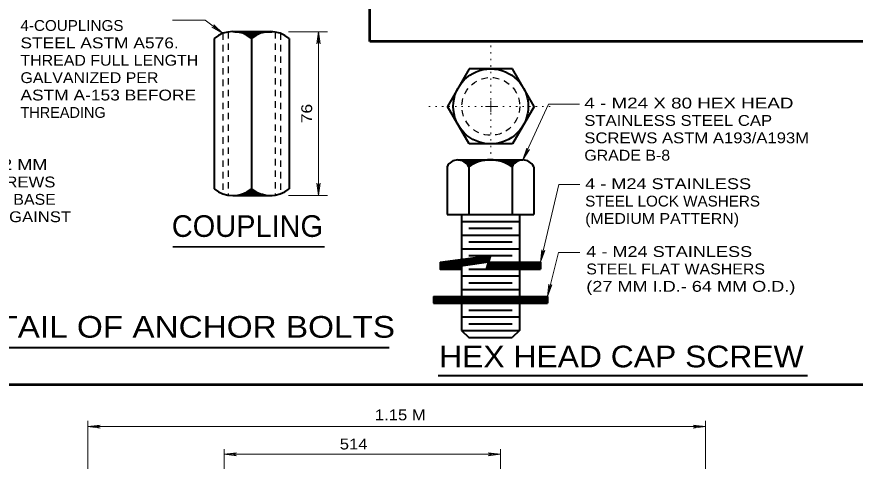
# Model space of a CAD drawing. Extents: x 312583 to 312854, y 144419 to 144597.
# Drawn here: x 312692.4 to 312751.3, y 144480.8 to 144512 of the extents above; entities that cross this region are included whole.
import ezdxf
from ezdxf.enums import TextEntityAlignment as Align

# ---------------------------------------------------------------- set-up
doc = ezdxf.new("R2010")
doc.units = 0
doc.header["$LTSCALE"] = 0.3
doc.linetypes.add('DOTTED', pattern=[1.5, 0.3, -1.2])
doc.linetypes.add('SHORT_DASHED', pattern=[2.7, 1.5, -1.2])
doc.layers.add('1', color=7, linetype='Continuous', lineweight=13)

msp = doc.modelspace()

# ---------------------------------------------------------------- linework, layer by layer
at = {"layer": '1', "lineweight": 53}
for p, q in [((312717.1857, 144510.2401), (312717.1857, 144585.0846)), ((312796.3473, 144510.2401), (312717.1857, 144510.2401)), ((312693.5008, 144486.1644), (312666.9226, 144486.1644)), ((312796.3473, 144486.1644), (312693.5008, 144486.1644))]:
    msp.add_line(p, q, dxfattribs=at)
at = {"layer": '1'}
for p, q in [((312703.3293, 144511.7369), (312705.637, 144511.7369)), ((312706.8636, 144510.8169), (312705.637, 144511.7369)), ((312706.235, 144511.4226), (312706.3883, 144511.1696)), ((312706.8636, 144510.8169), (312706.235, 144511.4226)), ((312706.1046, 144511.2539), (312706.3883, 144511.1696)), ((312706.8636, 144510.8169), (312706.1046, 144511.2539)), ((312711.4699, 144510.9373), (312714.2222, 144510.9373)), ((312713.5873, 144510.9472), (312713.48, 144510.0809)), ((312713.5873, 144499.4472), (312713.5873, 144510.9472)), ((312713.5873, 144510.9472), (312713.6946, 144510.0809)), ((312713.48, 144510.0809), (312713.5873, 144510.3569)), ((312713.6946, 144510.0809), (312713.5873, 144510.3569)), ((312725.6875, 144505.6974), (312725.6875, 144506.0807)), ((312725.6875, 144505.6974), (312725.3042, 144505.6974)), ((312725.6875, 144505.6974), (312726.0708, 144505.6974)), ((312725.6875, 144505.6974), (312725.6875, 144505.3141)), ((312727.9354, 144501.9475), (312729.7401, 144505.85)), ((312729.7401, 144505.85), (312731.907, 144505.85)), ((312727.9354, 144501.9475), (312728.2037, 144502.7755)), ((312727.9354, 144501.9475), (312728.3954, 144502.6835)), ((312728.2037, 144502.7755), (312728.1884, 144502.4842)), ((312728.3954, 144502.6835), (312728.1884, 144502.4842)), ((312713.48, 144500.3136), (312713.5873, 144500.0376)), ((312713.5873, 144499.4472), (312713.48, 144500.3136)), ((312713.6946, 144500.3136), (312713.5873, 144500.0376)), ((312713.5873, 144499.4472), (312713.6946, 144500.3136)), ((312729.1774, 144494.7639), (312730.4706, 144500.2113)), ((312730.4706, 144500.2113), (312731.9379, 144500.2113)), ((312711.4699, 144499.4373), (312714.2222, 144499.4373)), ((312729.1774, 144494.7639), (312729.2771, 144495.6302)), ((312729.1774, 144494.7639), (312729.4841, 144495.5842)), ((312729.2771, 144495.6302), (312729.3154, 144495.3389)), ((312729.4841, 144495.5842), (312729.3154, 144495.3389)), ((312729.6604, 144492.3642), (312730.4415, 144495.4503)), ((312730.4415, 144495.4503), (312731.9379, 144495.4503)), ((312729.6604, 144492.3642), (312729.7677, 144493.2305)), ((312729.6604, 144492.3642), (312729.9747, 144493.1769)), ((312729.7677, 144493.2305), (312729.8061, 144492.9315)), ((312729.9747, 144493.1769), (312729.8061, 144492.9315)), ((312697.3886, 144472.3419), (312697.3886, 144483.6272)), ((312697.3886, 144483.2285), (312698.2549, 144483.3359)), ((312697.3886, 144483.2285), (312740.7513, 144483.2285)), ((312697.3886, 144483.2285), (312698.2549, 144483.1212)), ((312698.2549, 144483.3359), (312697.9789, 144483.2285)), ((312698.2549, 144483.1212), (312697.9789, 144483.2285)), ((312739.8849, 144483.3359), (312740.1609, 144483.2285)), ((312740.7513, 144483.2285), (312739.8849, 144483.3359)), ((312739.8849, 144483.1212), (312740.1609, 144483.2285)), ((312740.7513, 144483.2285), (312739.8849, 144483.1212)), ((312740.7513, 144472.7252), (312740.7513, 144483.6272)), ((312706.9719, 144472.8402), (312706.9719, 144481.6415)), ((312706.9719, 144481.2889), (312707.8383, 144481.3962)), ((312707.8383, 144481.3962), (312707.5623, 144481.2889)), ((312725.5099, 144481.3962), (312725.7859, 144481.2889)), ((312726.3763, 144481.2889), (312725.5099, 144481.3962)), ((312726.3763, 144468.1712), (312726.3763, 144481.6415)), ((312706.9719, 144481.2889), (312726.3763, 144481.2889)), ((312706.9719, 144481.2889), (312707.8383, 144481.1815)), ((312707.8383, 144481.1815), (312707.5623, 144481.2889)), ((312725.5099, 144481.1815), (312725.7859, 144481.2889)), ((312726.3763, 144481.2889), (312725.5099, 144481.1815))]:
    msp.add_line(p, q, dxfattribs=at)
at = {"layer": '1', "linetype": 'SHORT_DASHED', "lineweight": 25}
for p, q in [((312706.8636, 144510.8169), (312706.8636, 144499.5699)), ((312707.247, 144510.9166), (312707.247, 144499.4702)), ((312710.536, 144510.9166), (312710.536, 144499.4702)), ((312710.927, 144510.8169), (312710.927, 144499.5776))]:
    msp.add_line(p, q, dxfattribs=at)
at = {"layer": '1', "lineweight": 40}
for p, q in [((312707.5766, 144510.9472), (312710.2063, 144510.9472)), ((312707.7055, 144510.9373), (312710.3352, 144510.9373)), ((312708.8876, 144510.9472), (312708.8876, 144499.4472)), ((312706.258, 144510.4642), (312706.258, 144499.9226)), ((312711.525, 144510.4642), (312711.525, 144499.9226)), ((312724.1618, 144508.3347), (312722.6438, 144505.6974)), ((312727.2055, 144508.3347), (312724.1618, 144508.3347)), ((312728.7312, 144505.6974), (312727.2055, 144508.3347)), ((312724.1618, 144503.0601), (312722.6438, 144505.6974)), ((312728.7312, 144505.6974), (312727.2055, 144503.0601)), ((312727.2055, 144503.0601), (312724.1618, 144503.0601)), ((312723.3737, 144501.9475), (312727.9354, 144501.9475)), ((312722.6147, 144501.4645), (312722.6147, 144498.1142)), ((312724.1327, 144501.4645), (312724.1327, 144498.1142)), ((312727.1764, 144501.4645), (312727.1764, 144498.1142)), ((312728.7021, 144501.4645), (312728.7021, 144498.1142)), ((312707.5766, 144499.4472), (312710.2063, 144499.4472)), ((312707.7055, 144499.4373), (312710.3352, 144499.4373)), ((312722.6147, 144498.1142), (312728.7021, 144498.1142)), ((312723.6267, 144498.1142), (312723.6267, 144489.9645)), ((312727.6901, 144498.1142), (312727.6901, 144489.9645)), ((312723.6267, 144497.6312), (312727.6901, 144497.6312)), ((312723.6267, 144496.6729), (312727.6901, 144496.6729)), ((312724.1327, 144497.1559), (312727.1764, 144497.1559)), ((312724.1327, 144496.1975), (312727.1764, 144496.1975)), ((312723.6267, 144495.7145), (312727.6901, 144495.7145)), ((312724.1327, 144495.2392), (312727.1764, 144495.2392)), ((312722.1317, 144494.7639), (312722.1317, 144494.2809)), ((312725.5127, 144494.7639), (312729.1774, 144494.7639)), ((312729.1774, 144494.7562), (312729.1774, 144494.2809)), ((312723.6267, 144493.7979), (312727.6901, 144493.7979)), ((312724.1327, 144494.2809), (312727.1764, 144494.2809)), ((312725.3594, 144494.2809), (312729.1774, 144494.2809)), ((312724.1327, 144493.3225), (312727.1764, 144493.3225)), ((312723.6267, 144492.8395), (312727.6901, 144492.8395)), ((312721.6564, 144492.3642), (312729.6604, 144492.3642)), ((312721.6564, 144492.3642), (312721.6564, 144491.8812)), ((312721.6564, 144492.2415), (312729.6604, 144492.2415)), ((312721.6564, 144492.1112), (312729.6604, 144492.1112)), ((312721.6564, 144491.9885), (312729.6604, 144491.9885)), ((312729.6604, 144492.3642), (312729.6604, 144491.8812)), ((312721.6564, 144491.8812), (312729.6604, 144491.8812)), ((312724.1327, 144491.4059), (312727.1764, 144491.4059)), ((312723.6267, 144490.9229), (312727.6901, 144490.9229)), ((312724.1327, 144490.4475), (312727.1764, 144490.4475)), ((312723.6267, 144489.9645), (312727.6901, 144489.9645)), ((312723.6267, 144489.9645), (312724.1327, 144489.4892)), ((312727.6901, 144489.9645), (312727.1764, 144489.4892)), ((312724.1327, 144489.4892), (312727.1764, 144489.4892)), ((312687.7256, 144488.7777), (312718.5583, 144488.7777)), ((312721.9784, 144486.8212), (312747.9299, 144486.8212))]:
    msp.add_line(p, q, dxfattribs=at)
at = {"layer": '1', "linetype": 'DOTTED'}
for p, q in [((312725.6875, 144505.7199), (312725.6875, 144509.9907)), ((312725.1125, 144505.6974), (312721.2792, 144505.6974)), ((312725.6875, 144505.6974), (312725.6875, 144501.8641)), ((312726.0708, 144505.6974), (312729.9041, 144505.6974))]:
    msp.add_line(p, q, dxfattribs=at)
at = {"layer": '1', "lineweight": 35}
msp.add_line((312703.3583, 144495.8417), (312714.0181, 144495.8417), dxfattribs=at)
at = {"layer": '1', "lineweight": 40}
for points in [[(312707.9293, 144510.9319), (312709.8766, 144510.9319), (312709.6543, 144510.8859), (312709.4473, 144510.8246), (312709.225, 144510.7326), (312709.087, 144510.6559), (312708.9106, 144510.5256), (312708.8876, 144510.5026), (312708.5273, 144510.7402), (312708.2053, 144510.8706), (312708.0136, 144510.9089), (312709.7386, 144510.9242), (312709.593, 144510.9012), (312709.4473, 144510.8629), (312709.2326, 144510.7862), (312709.018, 144510.6712), (312708.9566, 144510.6099), (312708.8876, 144510.5409), (312708.558, 144510.7556), (312708.2053, 144510.8936), (312709.478, 144510.9012), (312709.179, 144510.7862), (312708.8953, 144510.6099), (312708.328, 144510.8706), (312709.3476, 144510.8859), (312708.8953, 144510.5869), (312708.443, 144510.8476), (312709.2633, 144510.8629), (312708.9106, 144510.6712), (312708.6193, 144510.8169), (312709.133, 144510.8322), (312708.8876, 144510.7479), (312708.5963, 144510.7939), (312708.7803, 144510.6942), (312708.8263, 144510.8092), (312708.8723, 144510.6329), (312708.995, 144510.7709), (312709.0716, 144510.7786), (312709.156, 144510.8092)], [(312723.5654, 144501.9322), (312725.2674, 144501.9322), (312724.9761, 144501.8709), (312724.7844, 144501.8325), (312724.4701, 144501.7099), (312724.1404, 144501.4952), (312724.0331, 144501.6869), (312723.8874, 144501.7942), (312723.6421, 144501.9169), (312725.1294, 144501.9169), (312724.7077, 144501.8325), (312724.3934, 144501.6869), (312724.1634, 144501.5412), (312723.9181, 144501.7712), (312723.7417, 144501.8939), (312724.9454, 144501.9015), (312724.5314, 144501.7789), (312724.1634, 144501.5795), (312723.8261, 144501.8709), (312724.8074, 144501.8862), (312724.1404, 144501.6179), (312723.8797, 144501.8555), (312724.7001, 144501.8709), (312724.1251, 144501.6562), (312723.9487, 144501.8402), (312724.5774, 144501.8479), (312724.1404, 144501.7022), (312724.0254, 144501.8095), (312724.4164, 144501.8172), (312724.1634, 144501.7252), (312724.1021, 144501.8019), (312724.2707, 144501.7942), (312724.1557, 144501.7635)], [(312727.7514, 144501.9322), (312726.0417, 144501.9322), (312726.3331, 144501.8709), (312726.5247, 144501.8325), (312726.8467, 144501.7099), (312727.1687, 144501.4952), (312727.2837, 144501.6869), (312727.4217, 144501.7942), (312727.6747, 144501.9169), (312726.1797, 144501.9169), (312726.6091, 144501.8325), (312726.9157, 144501.6869), (312727.1534, 144501.5412), (312727.3987, 144501.7712), (312727.5674, 144501.8939), (312726.3714, 144501.9015), (312726.7854, 144501.7789), (312727.1534, 144501.5795), (312727.4907, 144501.8709), (312726.5017, 144501.8862), (312727.1764, 144501.6179), (312727.4294, 144501.8555), (312726.6091, 144501.8709), (312727.1841, 144501.6562), (312727.3604, 144501.8402), (312726.7317, 144501.8479), (312727.1764, 144501.7022), (312727.2914, 144501.8095), (312726.9004, 144501.8172), (312727.1457, 144501.7252), (312727.2147, 144501.8019), (312727.0384, 144501.7942), (312727.1534, 144501.7635)], [(312707.9293, 144499.4626), (312709.8766, 144499.4549), (312709.6543, 144499.5086), (312709.4473, 144499.5622), (312709.225, 144499.6542), (312709.087, 144499.7309), (312708.9106, 144499.8612), (312708.8876, 144499.8842), (312708.5273, 144499.6466), (312708.2053, 144499.5239), (312708.0136, 144499.4779), (312709.7386, 144499.4702), (312709.593, 144499.4856), (312709.4473, 144499.5239), (312709.2326, 144499.6006), (312709.018, 144499.7156), (312708.9566, 144499.7846), (312708.8876, 144499.8536), (312708.558, 144499.6312), (312708.2053, 144499.5009), (312709.478, 144499.4932), (312709.179, 144499.6006), (312708.8953, 144499.7846), (312708.328, 144499.5162), (312709.3476, 144499.5086), (312708.8953, 144499.8076), (312708.443, 144499.5392), (312709.2633, 144499.5239), (312708.9106, 144499.7232), (312708.6193, 144499.5699), (312709.133, 144499.5622), (312708.8876, 144499.6389), (312708.5963, 144499.5929), (312708.7803, 144499.7002), (312708.8263, 144499.5776), (312708.8723, 144499.7539), (312708.995, 144499.6159), (312709.0716, 144499.6082), (312709.156, 144499.5776)], [(312722.1317, 144494.7639), (312725.6584, 144495.2392), (312725.3594, 144494.2809)], [(312723.6267, 144494.2809), (312722.1547, 144494.3422), (312722.2007, 144494.7179), (312725.5587, 144495.1625), (312725.4437, 144494.8022), (312723.6037, 144494.5415), (312723.5654, 144494.3499), (312722.2237, 144494.4035), (312722.2391, 144494.6489), (312725.4821, 144495.0935), (312725.3977, 144494.8482), (312723.5271, 144494.5492), (312723.4887, 144494.4035), (312722.2774, 144494.4495), (312722.2774, 144494.5722), (312725.3441, 144495.0169), (312725.3517, 144494.9249), (312723.5424, 144494.6029), (312723.4274, 144494.5492), (312723.0441, 144494.4649), (312722.3541, 144494.5032), (312725.2597, 144494.9632), (312722.8141, 144494.4955)], [(312725.5127, 144494.7639), (312722.1317, 144494.2809), (312723.6267, 144494.2809)], [(312725.4437, 144494.3345), (312729.1084, 144494.3345), (312729.1084, 144494.7102), (312725.5664, 144494.6872), (312725.4514, 144494.4035), (312729.0547, 144494.3882), (312729.0394, 144494.6412), (312725.6124, 144494.6182), (312725.5357, 144494.4495), (312728.9857, 144494.4725), (312728.9321, 144494.5569), (312728.9167, 144494.5952), (312725.6354, 144494.5645), (312725.5894, 144494.4955), (312728.9091, 144494.5109)]]:
    msp.add_lwpolyline(points, dxfattribs=at)
msp.add_circle((312725.6837, 144505.6974), 2.6335, dxfattribs=at)
at = {"layer": '1', "linetype": 'SHORT_DASHED', "lineweight": 25}
msp.add_circle((312725.6837, 144505.6974), 2.0317, dxfattribs=at)
at = {"layer": '1', "lineweight": 40}
for centre, radius, start, end in [((312707.5709, 144508.8946), 2.0488, 50.00693, 129.99306), ((312710.2044, 144508.8946), 2.0488, 50.00694, 129.99307), ((312723.3718, 144501.1), 0.8438, 25.60064, 154.39936), ((312725.6546, 144499.2874), 2.6562, 55.04559, 124.95441), ((312727.9373, 144501.1), 0.8438, 25.60064, 154.39936), ((312707.5709, 144501.4922), 2.0488, 230.00694, 309.99307), ((312710.2044, 144501.4922), 2.0488, 230.00693, 309.99306)]:
    msp.add_arc(centre, radius, start, end, dxfattribs=at)

# ---------------------------------------------------------------- texts
at = {"layer": '1'}
for s, width, p in [('4-COUPLINGS', 1.05, (312692.6567, 144510.9923)), ('STEEL ASTM A576.', 1.2, (312692.6567, 144509.7723)), ('THREAD FULL LENGTH', 1.1, (312692.6567, 144508.5523)), ('GALVANIZED PER', 1.1, (312692.6567, 144507.3323)), ('ASTM A-153 BEFORE ', 1.2, (312692.6567, 144506.1123)), ('4 - M24 X 80 HEX HEAD', 1.3, (312732.2517, 144505.5499)), ('STAINLESS STEEL CAP', 1.15, (312732.2517, 144504.3299)), ('SCREWS ASTM A193/A193M', 1.15, (312732.2517, 144503.1099)), ('GRADE B-8', 1.1, (312732.2517, 144501.8899)), ('ANCHOR BOLTS TO BE SET 29   2 MM', 1.25, (312671.5374, 144501.2346)), ('INTO COUPLINGS SO THAT CAP SCREWS', 1.15, (312671.5374, 144500.0146)), ('4 - M24 STAINLESS', 1.25, (312732.3131, 144499.8919)), ('WHEN TIGHTENED,  SECURING POLE BASE', 1.1, (312671.5374, 144498.7946)), ('STEEL LOCK WASHERS', 1.05, (312732.3131, 144498.6719)), ('TO FOUNDATION, WILL NOT BUTT AGAINST', 1.15, (312671.5374, 144497.5746)), ('(MEDIUM PATTERN)', 1.1, (312732.3131, 144497.4519)), ('4 - M24 STAINLESS', 1.25, (312732.3897, 144495.1309)), ('STEEL FLAT WASHERS', 1.1, (312732.3897, 144493.9109)), ('(27 MM I.D.- 64 MM O.D.)', 1.25, (312732.3897, 144492.6909)), ('1.15 M', 1.15, (312717.5422, 144483.6729)), ('514 ', 1.15, (312715.08, 144481.6259))]:
    msp.add_text(s, height=0.76, dxfattribs=dict(at, width=width)).set_placement(p)
msp.add_text('THREADING', height=0.76, dxfattribs=at).set_placement((312692.6567, 144504.8923))
at = {"layer": '1', "width": 1.2}
msp.add_text('76 ', height=0.76, rotation=90, dxfattribs=at).set_placement((312713.1381, 144504.5165))
at = {"layer": '1'}
msp.add_text('COUPLING', height=1.52, dxfattribs=at).set_placement((312708.5952, 144496.5402), align=Align.CENTER)
for s, width, p in [('DETAIL OF ANCHOR BOLTS', 1.15, (312703.3752, 144489.4688)), ('HEX HEAD CAP SCREW', 1.1, (312734.854, 144487.3877))]:
    msp.add_text(s, height=1.52, dxfattribs=dict(at, width=width)).set_placement(p, align=Align.CENTER)

doc.saveas('drawing.dxf')
